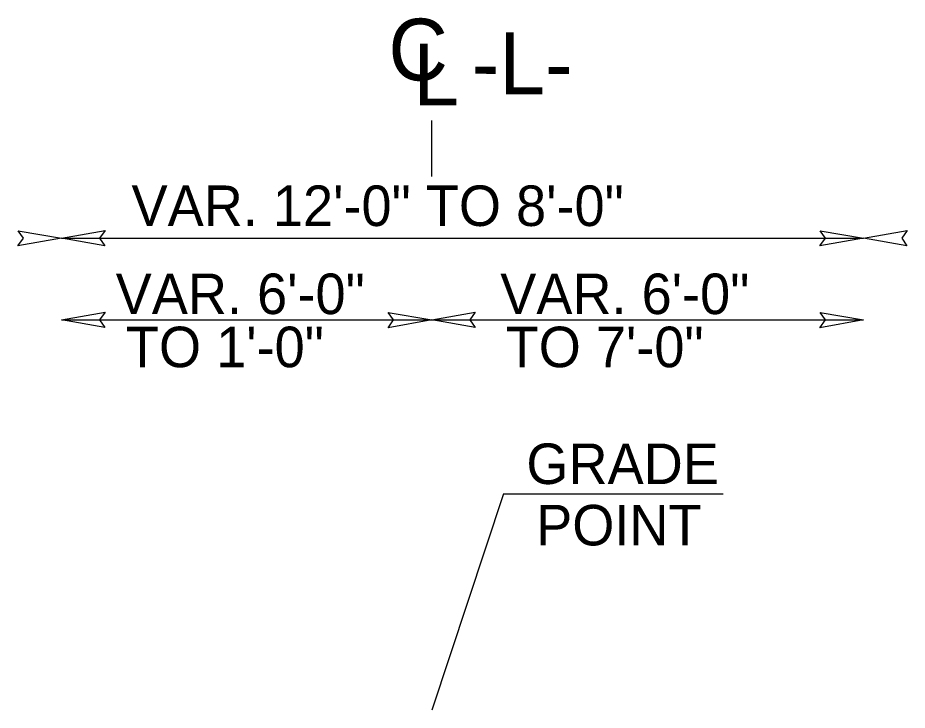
# Model space of a CAD drawing. Extents: x 1901718 to 1902220, y 193828 to 194187.
# Drawn here: x 1901908.82 to 1901923.23, y 194133.26 to 194144.48 of the extents above; entities that cross this region are included whole.
import ezdxf

# ---------------------------------------------------------------- set-up
doc = ezdxf.new("R2010")
doc.units = 0
for name, color, linetype in [('Old_Level_1', 7, 'Continuous'), ('Old_Level_2', 7, 'Continuous'), ('Old_Level_3', 7, 'Continuous'), ('Prop Dimension', 7, 'Continuous'), ('Typical Terminator CELL', 7, 'Continuous')]:
    doc.layers.add(name, color=color, linetype=linetype)

# ---------------------------------------------------------------- blocks, each defined once
blk = doc.blocks.new('TERMINATOR')
at = {"layer": 'Typical Terminator CELL'}
blk.add_lwpolyline([(-0.4687, 0.0807), (0, 0), (-0.4713, -0.0833), (-0.4114, 0)], close=True, dxfattribs=at)

msp = doc.modelspace()

# ---------------------------------------------------------------- linework, layer by layer
at = {"layer": 'Old_Level_1'}
msp.add_line((1901915.526, 194141.91), (1901915.526, 194142.817), dxfattribs=at)
at = {"layer": 'Old_Level_3'}
for q in [(1901915.526, 194133.264), (1901920.252, 194136.769)]:
    msp.add_line((1901916.688, 194136.769), q, dxfattribs=at)
at = {"layer": 'Prop Dimension'}
for p, q in [((1901909.526, 194140.908), (1901922.526, 194140.908)), ((1901909.526, 194139.584), (1901915.526, 194139.584)), ((1901915.526, 194139.584), (1901922.526, 194139.584))]:
    msp.add_line(p, q, dxfattribs=at)

# ---------------------------------------------------------------- block references
at = {"layer": 'Prop Dimension', "xscale": 1.5, "yscale": 1.5}
for p in [(1901909.526, 194140.908), (1901922.526, 194140.908), (1901915.526, 194139.584), (1901922.526, 194139.584)]:
    msp.add_blockref('TERMINATOR', p, dxfattribs=at)
at = {"layer": 'Prop Dimension', "xscale": 1.5, "yscale": 1.5, "rotation": 180}
for p in [(1901909.526, 194140.908), (1901922.526, 194140.908), (1901909.526, 194139.584), (1901915.526, 194139.584)]:
    msp.add_blockref('TERMINATOR', p, dxfattribs=at)

# ---------------------------------------------------------------- texts
at = {"layer": 'Old_Level_2'}
msp.add_text('C', height=1, dxfattribs=at).set_placement((1901914.824, 194143.463))
for s, p in [('-L-', (1901916.175, 194143.241)), ('L', (1901915.226, 194143.059))]:
    msp.add_text(s, height=1, rotation=359.9469, dxfattribs=at).set_placement(p)
at = {"layer": 'Old_Level_3'}
for s, p in [('GRADE', (1901917.061, 194136.927)), ('POINT', (1901917.219, 194135.933))]:
    msp.add_text(s, height=0.656, dxfattribs=at).set_placement(p)
at = {"layer": 'Prop Dimension'}
for s, p in [('VAR. 12\'-0" TO 8\'-0"', (1901910.662, 194141.106)), ('VAR. 6\'-0" ', (1901910.405, 194139.679)), ('VAR. 6\'-0" ', (1901916.637, 194139.679)), ('TO 1\'-0"', (1901910.571, 194138.819)), ('TO 7\'-0"', (1901916.725, 194138.819))]:
    msp.add_text(s, height=0.656, dxfattribs=at).set_placement(p)

doc.saveas('drawing.dxf')
